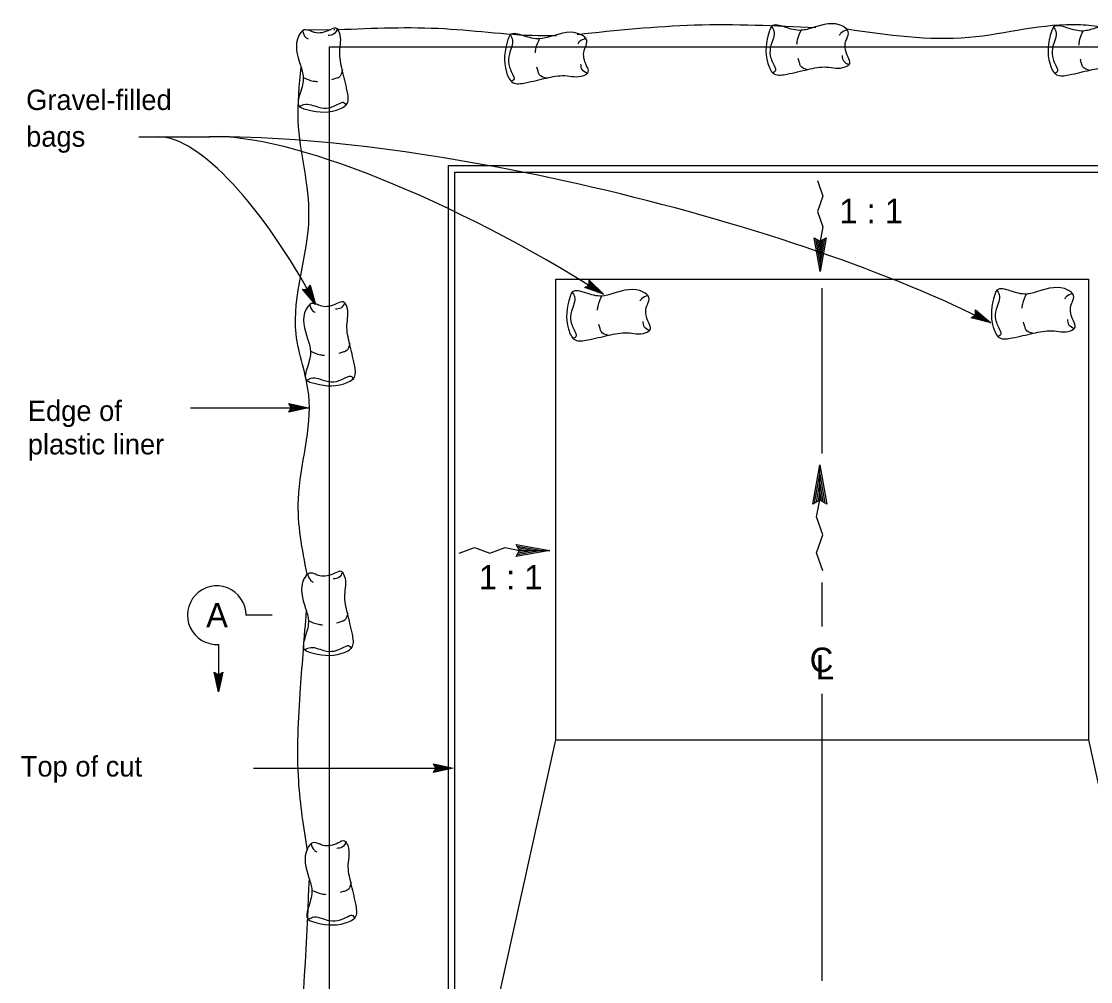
# Model space of a CAD drawing. Extents: x 6708826 to 6711089, y 1868571 to 1869537.
# Drawn here: x 6708829.8 to 6709144.3, y 1868819.1 to 1869101.6 of the extents above; entities that cross this region are included whole.
import ezdxf

# ---------------------------------------------------------------- set-up
doc = ezdxf.new("R2010")
doc.units = 0
for name, color, linetype in [('56 Stg 3 Anno', 7, 'Continuous'), ('57 Undefined', 7, 'Continuous'), ('60 Nongeo Data', 7, 'Continuous')]:
    doc.layers.add(name, color=color, linetype=linetype)

msp = doc.modelspace()

# ---------------------------------------------------------------- linework, layer by layer
at = {"layer": '56 Stg 3 Anno'}
for p, q in [((6708864.35, 1869067.62), (6708885.21, 1869067.62)), ((6709064.77, 1869028.01), (6709063.02, 1869037.91)), ((6709063.02, 1869037.91), (6709064.77, 1869036.89)), ((6709064.77, 1869030.38), (6709063.48, 1869037.64)), ((6709064.77, 1869032.73), (6709063.95, 1869037.36)), ((6709064.77, 1869035.13), (6709064.42, 1869037.09)), ((6709066.51, 1869037.91), (6709064.77, 1869028.01)), ((6709064.77, 1869036.89), (6709066.51, 1869037.91)), ((6709066.05, 1869037.64), (6709064.77, 1869030.38)), ((6709065.58, 1869037.36), (6709064.77, 1869032.73)), ((6709065.11, 1869037.09), (6709064.77, 1869035.13)), ((6708914, 1869022.68), (6708914.77, 1869023.97)), ((6708914.37, 1869023.26), (6708915.12, 1869020.62)), ((6708914.57, 1869023.63), (6708915.74, 1869019.46)), ((6708914.77, 1869023.97), (6708914.77, 1869023.97)), ((6708914.77, 1869023.97), (6708916.37, 1869018.29)), ((6708995.5, 1869023.3), (6708996.83, 1869023.97)), ((6709001.06, 1869021.32), (6708995.5, 1869023.3)), ((6708995.5, 1869023.3), (6708995.5, 1869023.3)), ((6708999.93, 1869022.03), (6708995.88, 1869023.47)), ((6708998.81, 1869022.73), (6708996.2, 1869023.66)), ((6708997.69, 1869023.44), (6708996.57, 1869023.84)), ((6708996.83, 1869023.97), (6708996.86, 1869025.47)), ((6708996.83, 1869024.29), (6708997.69, 1869023.44)), ((6708996.86, 1869025.47), (6708996.86, 1869025.47)), ((6708996.86, 1869025.47), (6709001.06, 1869021.32)), ((6708996.86, 1869025.07), (6708999.94, 1869022.03)), ((6708996.86, 1869024.66), (6708998.81, 1869022.73)), ((6708916.37, 1869018.29), (6708912.52, 1869022.75)), ((6708912.52, 1869022.75), (6708912.52, 1869022.75)), ((6708912.52, 1869022.75), (6708914, 1869022.68)), ((6708915.73, 1869019.46), (6708912.93, 1869022.72)), ((6708915.12, 1869020.62), (6708913.3, 1869022.73)), ((6708914.49, 1869021.79), (6708913.71, 1869022.69)), ((6708914.16, 1869022.96), (6708914.49, 1869021.79)), ((6709001.06, 1869021.32), (6709001.06, 1869021.32)), ((6709065.3, 1868974.39), (6709065.3, 1869023.08)), ((6708916.37, 1869018.29), (6708916.37, 1869018.29)), ((6709109.21, 1869014.39), (6709110.49, 1869015.17)), ((6709114.91, 1869012.86), (6709109.21, 1869014.39)), ((6709109.21, 1869014.39), (6709109.21, 1869014.39)), ((6709113.73, 1869013.47), (6709109.57, 1869014.59)), ((6709112.56, 1869014.09), (6709109.88, 1869014.81)), ((6709111.39, 1869014.7), (6709110.24, 1869015.01)), ((6709110.49, 1869015.17), (6709110.4, 1869016.66)), ((6709110.4, 1869016.66), (6709110.4, 1869016.66)), ((6709110.4, 1869016.66), (6709114.91, 1869012.86)), ((6709110.43, 1869016.26), (6709113.74, 1869013.47)), ((6709110.46, 1869015.48), (6709111.39, 1869014.7)), ((6709110.47, 1869015.85), (6709112.56, 1869014.09)), ((6709114.91, 1869012.86), (6709114.91, 1869012.86)), ((6708909.24, 1868987.85), (6708908.47, 1868989.14)), ((6708908.47, 1868989.14), (6708908.47, 1868989.14)), ((6708908.47, 1868989.14), (6708914.23, 1868987.85)), ((6708908.68, 1868988.8), (6708912.91, 1868987.85)), ((6708879.54, 1868987.85), (6708914.23, 1868987.85)), ((6708914.23, 1868987.85), (6708908.47, 1868986.58)), ((6708908.47, 1868986.58), (6708909.24, 1868987.85)), ((6708908.47, 1868986.58), (6708908.47, 1868986.58)), ((6708912.89, 1868987.85), (6708908.7, 1868986.92)), ((6708911.58, 1868987.85), (6708908.87, 1868987.25)), ((6708908.9, 1868988.45), (6708911.58, 1868987.85)), ((6708909.07, 1868988.12), (6708910.25, 1868987.86)), ((6708910.25, 1868987.86), (6708909.09, 1868987.6)), ((6708914.23, 1868987.85), (6708914.23, 1868987.85)), ((6709062.6, 1868959.55), (6709064.64, 1868971.09)), ((6709064.64, 1868971.09), (6709066.68, 1868959.55)), ((6709063.14, 1868959.86), (6709064.64, 1868968.33)), ((6709064.64, 1868968.33), (6709066.14, 1868959.86)), ((6709063.69, 1868960.18), (6709064.64, 1868965.59)), ((6709064.64, 1868965.59), (6709065.59, 1868960.18)), ((6709064.64, 1868960.73), (6709062.6, 1868959.55)), ((6709064.24, 1868960.5), (6709064.64, 1868962.78)), ((6709064.64, 1868962.78), (6709065.04, 1868960.5)), ((6709066.68, 1868959.55), (6709064.64, 1868960.73)), ((6708975.35, 1868947.67), (6708985.24, 1868945.92)), ((6708976.36, 1868945.92), (6708975.35, 1868947.67)), ((6708985.24, 1868945.92), (6708975.35, 1868944.18)), ((6708975.35, 1868944.18), (6708976.36, 1868945.92)), ((6708975.62, 1868947.21), (6708982.88, 1868945.92)), ((6708982.88, 1868945.92), (6708975.62, 1868944.64)), ((6708975.89, 1868946.74), (6708980.53, 1868945.92)), ((6708980.53, 1868945.92), (6708975.89, 1868945.11)), ((6708976.16, 1868946.27), (6708978.12, 1868945.92)), ((6708978.12, 1868945.92), (6708976.16, 1868945.58)), ((6709065.3, 1868923.55), (6709065.3, 1868936.5)), ((6708903.6, 1868926.88), (6708895.87, 1868926.88)), ((6708887.81, 1868918.26), (6708887.81, 1868904.33)), ((6708887.81, 1868904.33), (6708886.53, 1868910.09)), ((6708886.53, 1868910.09), (6708886.53, 1868910.09)), ((6708886.53, 1868910.09), (6708887.81, 1868909.32)), ((6708887.81, 1868909.32), (6708889.09, 1868910.09)), ((6708889.09, 1868910.09), (6708887.81, 1868904.33)), ((6708889.09, 1868910.09), (6708889.09, 1868910.09)), ((6708887.8, 1868905.66), (6708886.87, 1868909.86)), ((6708887.81, 1868906.98), (6708887.21, 1868909.69)), ((6708887.81, 1868908.31), (6708887.55, 1868909.47)), ((6708888.75, 1868909.88), (6708887.81, 1868905.65)), ((6708888.41, 1868909.66), (6708887.81, 1868906.98)), ((6708888.07, 1868909.49), (6708887.81, 1868908.31)), ((6708887.81, 1868904.33), (6708887.81, 1868904.33)), ((6709065.3, 1868819.27), (6709065.3, 1868903.71)), ((6708898.05, 1868881.86), (6708955.73, 1868881.86)), ((6708951.81, 1868881.86), (6708951.04, 1868883.15)), ((6708951.04, 1868883.15), (6708951.04, 1868883.15)), ((6708951.04, 1868883.15), (6708956.8, 1868881.86)), ((6708956.8, 1868881.86), (6708951.04, 1868880.58)), ((6708951.04, 1868880.58), (6708951.81, 1868881.86)), ((6708951.25, 1868882.81), (6708955.48, 1868881.86)), ((6708955.47, 1868881.86), (6708951.27, 1868880.93)), ((6708954.15, 1868881.86), (6708951.44, 1868881.26)), ((6708951.47, 1868882.46), (6708954.15, 1868881.86)), ((6708951.64, 1868882.13), (6708952.82, 1868881.86)), ((6708952.82, 1868881.86), (6708951.66, 1868881.61)), ((6708956.8, 1868881.86), (6708956.8, 1868881.86)), ((6708951.04, 1868880.59), (6708951.04, 1868880.59))]:
    msp.add_line(p, q, dxfattribs=at)
for points in [[(6709063.95, 1869054.7), (6709065.58, 1869050.17), (6709063.95, 1869045.64), (6709065.58, 1869041.11), (6709064.77, 1869036.89), (6709064.77, 1869028.01)], [(6709065.59, 1868939.96), (6709063.69, 1868945.24), (6709065.59, 1868950.53), (6709063.69, 1868955.81), (6709064.64, 1868960.73), (6709064.64, 1868971.09)], [(6708958.55, 1868945.11), (6708963.08, 1868946.74), (6708967.61, 1868945.11), (6708972.14, 1868946.74), (6708976.36, 1868945.92), (6708985.24, 1868945.92)]]:
    msp.add_lwpolyline(points, dxfattribs=at)
msp.add_arc((6708887.28, 1868926.87), 8.62, 0.1055, 273.4975, dxfattribs=at)
for centre, major_axis, ratio, start_param, end_param in [((6708899.83, 1868997.73), (33.1, -69.04), 0.3155, 1.718556, 2.986785), ((6708995.51, 1869014.62), (158.62, -38.37), 0.230593, 0.776019, 2.395591), ((6708971.44, 1869005.23), (98.85, -57.14), 0.254227, 1.415085, 2.758276)]:
    msp.add_ellipse(centre, major_axis=major_axis, ratio=ratio, start_param=start_param, end_param=end_param, dxfattribs=at)
at = {"layer": '60 Nongeo Data'}
for p, q in [((6708912.74, 1869099.06), (6708920.79, 1869099.13)), ((6708921.7, 1869099.13), (6708922, 1869099.14)), ((6708990.43, 1869097.55), (6708990.45, 1869097.56)), ((6708987.05, 1868890.2), (6709143.66, 1868890.2))]:
    msp.add_line(p, q, dxfattribs=at)
for points in [[(6708920.45, 1868713.46), (6708920.45, 1869094.08), (6709209.91, 1869094.08), (6709209.91, 1868713.46)], [(6708955.42, 1868754.11), (6708955.42, 1869059.11), (6709174.94, 1869059.11), (6709174.94, 1868765.65)], [(6708957.34, 1868756.03), (6708957.34, 1869057.19), (6709173.02, 1869057.19), (6709173.02, 1868756.03)], [(6708987.05, 1869025.72), (6709143.66, 1869025.72)], [(6708987.05, 1868890.2), (6708987.05, 1869025.72)], [(6709143.66, 1869025.72), (6709143.66, 1868890.2)], [(6708957.38, 1868756.31), (6708987.05, 1868890.2)], [(6709143.66, 1868890.2), (6709172.98, 1868757)]]:
    msp.add_lwpolyline(points, dxfattribs=at)
for points in [[(6708915.06, 1869098.66), (6708913.02, 1869099.03), (6708911.43, 1869097.37), (6708911.88, 1869088.69), (6708912.71, 1869085.14), (6708911.81, 1869080.39), (6708911.65, 1869076.46), (6708912.94, 1869075.86), (6708922.55, 1869075.48), (6708925.65, 1869077.44), (6708925.65, 1869081.07), (6708924.21, 1869087.26), (6708923.46, 1869092.69), (6708923.38, 1869098.2), (6708922.32, 1869099.56), (6708920.51, 1869099.03), (6708916.04, 1869098.28), (6708914.83, 1869098.73)], [(6708912.49, 1869098.81), (6708913.47, 1869096.84), (6708914.15, 1869096.39)], [(6708922.85, 1869099.41), (6708921.64, 1869097.75), (6708920.05, 1869097.37)], [(6708922.89, 1869099.14), (6708954.23, 1869099.42), (6708983.7, 1869097.39), (6708987.22, 1869097.43)], [(6708995.72, 1869093.94), (6708996.11, 1869095.98), (6708994.47, 1869097.58), (6708985.78, 1869097.2), (6708982.23, 1869096.4), (6708977.48, 1869097.34), (6708973.55, 1869097.52), (6708972.94, 1869096.24), (6708972.48, 1869086.64), (6708974.42, 1869083.52), (6708978.05, 1869083.49), (6708984.25, 1869084.88), (6708989.69, 1869085.59), (6708995.2, 1869085.62), (6708996.57, 1869086.67), (6708996.06, 1869088.49), (6708995.34, 1869092.96), (6708995.8, 1869094.17)], [(6708993.28, 1869097.73), (6709027.81, 1869100.5), (6709063.48, 1869099.77)], [(6709072.63, 1869096.47), (6709073.03, 1869098.51), (6709071.38, 1869100.11), (6709062.69, 1869099.73), (6709059.14, 1869098.92), (6709054.39, 1869099.87), (6709050.47, 1869100.05), (6709049.85, 1869098.77), (6709049.4, 1869089.16), (6709051.34, 1869086.05), (6709054.96, 1869086.02), (6709061.16, 1869087.41), (6709066.6, 1869088.12), (6709072.11, 1869088.15), (6709073.48, 1869089.2), (6709072.97, 1869091.02), (6709072.25, 1869095.49), (6709072.71, 1869096.7)], [(6709050.47, 1869100.13), (6709051.13, 1869098.76), (6709050.27, 1869094.45), (6709050.09, 1869091.43), (6709051.43, 1869088.09), (6709051.65, 1869087.18), (6709050.66, 1869086.35)], [(6709059.14, 1869099), (6709057.98, 1869095.98), (6709057.82, 1869094.77)], [(6709072.81, 1869099.04), (6709070.84, 1869098.07), (6709070.38, 1869097.4)], [(6709072.66, 1869099.34), (6709108.46, 1869096.89), (6709141.34, 1869100.6), (6709147.79, 1869099.97)], [(6709155.6, 1869096.27), (6709155.99, 1869098.31), (6709154.34, 1869099.91), (6709145.66, 1869099.53), (6709142.1, 1869098.72), (6709137.35, 1869099.67), (6709133.43, 1869099.85), (6709132.81, 1869098.57), (6709132.36, 1869088.97), (6709134.3, 1869085.85), (6709137.92, 1869085.82), (6709144.13, 1869087.21), (6709149.57, 1869087.92), (6709155.08, 1869087.95), (6709156.45, 1869089), (6709155.93, 1869090.82), (6709155.21, 1869095.29), (6709155.68, 1869096.5)], [(6709133.43, 1869099.93), (6709134.1, 1869098.56), (6709133.23, 1869094.26), (6709133.06, 1869091.23), (6709134.39, 1869087.89), (6709134.61, 1869086.98), (6709133.62, 1869086.16)], [(6709142.1, 1869098.8), (6709140.95, 1869095.78), (6709140.79, 1869094.57)], [(6708973.55, 1869097.6), (6708974.22, 1869096.23), (6708973.36, 1869091.93), (6708973.18, 1869088.9), (6708974.51, 1869085.56), (6708974.73, 1869084.65), (6708973.75, 1869083.83)], [(6708982.23, 1869096.47), (6708981.07, 1869093.45), (6708980.91, 1869092.25)], [(6708995.89, 1869096.51), (6708993.92, 1869095.55), (6708993.46, 1869094.87)], [(6709061.24, 1869087.33), (6709058.98, 1869088.48), (6709058.69, 1869089.39), (6709058.32, 1869090.61)], [(6709073.33, 1869088.67), (6709071.68, 1869089.89), (6709071.31, 1869091.49)], [(6709144.2, 1869087.13), (6709141.94, 1869088.28), (6709141.65, 1869089.19), (6709141.28, 1869090.41)], [(6708913.83, 1868938.92), (6708911.3, 1868960.97), (6708914.33, 1868991.7), (6708910.64, 1869009.6), (6708914.41, 1869044.07), (6708911.27, 1869072.32), (6708912.14, 1869088.07)], [(6708924.29, 1869087.33), (6708923.15, 1869085.07), (6708922.25, 1869084.76), (6708921.03, 1869084.39)], [(6708984.32, 1869084.8), (6708982.07, 1869085.96), (6708981.77, 1869086.87), (6708981.4, 1869088.08)], [(6708996.41, 1869086.14), (6708994.76, 1869087.37), (6708994.4, 1869088.96)], [(6708912.64, 1869085.14), (6708915.66, 1869084.01), (6708916.87, 1869083.86)], [(6708911.58, 1869076.46), (6708912.94, 1869077.14), (6708917.25, 1869076.31), (6708920.28, 1869076.16), (6708923.61, 1869077.52), (6708924.51, 1869077.74), (6708925.35, 1869076.76)], [(6709013.99, 1869018.29), (6709014.39, 1869020.33), (6709012.74, 1869021.94), (6709004.05, 1869021.55), (6709000.5, 1869020.75), (6708995.75, 1869021.69), (6708991.82, 1869021.87), (6708991.21, 1869020.59), (6708990.76, 1869010.99), (6708992.69, 1869007.87), (6708996.32, 1869007.84), (6709002.52, 1869009.23), (6709007.96, 1869009.94), (6709013.47, 1869009.98), (6709014.84, 1869011.02), (6709014.33, 1869012.84), (6709013.61, 1869017.31), (6709014.07, 1869018.52)], [(6709138.9, 1869018.88), (6709139.3, 1869020.92), (6709137.65, 1869022.52), (6709128.96, 1869022.14), (6709125.41, 1869021.33), (6709120.66, 1869022.28), (6709116.73, 1869022.46), (6709116.12, 1869021.18), (6709115.67, 1869011.58), (6709117.6, 1869008.46), (6709121.23, 1869008.43), (6709127.43, 1869009.82), (6709132.87, 1869010.53), (6709138.38, 1869010.56), (6709139.75, 1869011.61), (6709139.24, 1869013.43), (6709138.52, 1869017.9), (6709138.98, 1869019.11)], [(6708991.82, 1869021.95), (6708992.49, 1869020.58), (6708991.63, 1869016.28), (6708991.45, 1869013.25), (6708992.79, 1869009.91), (6708993.01, 1869009), (6708992.02, 1869008.18)], [(6709000.5, 1869020.82), (6708999.34, 1869017.81), (6708999.18, 1869016.6)], [(6709014.16, 1869020.86), (6709012.19, 1869019.9), (6709011.74, 1869019.22)], [(6709116.73, 1869022.54), (6709117.4, 1869021.17), (6709116.54, 1869016.87), (6709116.36, 1869013.84), (6709117.7, 1869010.5), (6709117.91, 1869009.59), (6709116.93, 1869008.77)], [(6709125.41, 1869021.41), (6709124.25, 1869018.39), (6709124.09, 1869017.18)], [(6709139.07, 1869021.45), (6709137.1, 1869020.48), (6709136.64, 1869019.81)], [(6708917.18, 1869018.14), (6708915.14, 1869018.52), (6708913.55, 1869016.85), (6708914.01, 1869008.17), (6708914.84, 1869004.62), (6708913.93, 1868999.87), (6708913.78, 1868995.94), (6708915.06, 1868995.34), (6708924.67, 1868994.96), (6708927.77, 1868996.92), (6708927.77, 1869000.55), (6708926.34, 1869006.74), (6708925.58, 1869012.17), (6708925.5, 1869017.69), (6708924.45, 1869019.04), (6708922.63, 1869018.52), (6708918.17, 1869017.76), (6708916.96, 1869018.21)], [(6708914.61, 1869018.29), (6708915.59, 1869016.33), (6708916.27, 1869015.87)], [(6708924.98, 1869018.89), (6708923.76, 1869017.23), (6708922.18, 1869016.85)], [(6709139.6, 1869011.08), (6709137.94, 1869012.31), (6709137.58, 1869013.9)], [(6709002.6, 1869009.15), (6709000.34, 1869010.31), (6709000.04, 1869011.22), (6708999.68, 1869012.43)], [(6709014.69, 1869010.5), (6709013.04, 1869011.72), (6709012.67, 1869013.31)], [(6709127.5, 1869009.74), (6709125.25, 1869010.89), (6709124.95, 1869011.8), (6709124.59, 1869013.02)], [(6708914.76, 1869004.62), (6708917.79, 1869003.49), (6708919, 1869003.34)], [(6708926.41, 1869006.81), (6708925.28, 1869004.55), (6708924.37, 1869004.25), (6708923.16, 1869003.87)], [(6708913.7, 1868995.94), (6708915.06, 1868996.62), (6708919.38, 1868995.79), (6708922.4, 1868995.64), (6708925.73, 1868997), (6708926.64, 1868997.22), (6708927.47, 1868996.24)], [(6708916.58, 1868938.83), (6708914.53, 1868939.21), (6708912.94, 1868937.55), (6708913.4, 1868928.87), (6708914.23, 1868925.32), (6708913.32, 1868920.56), (6708913.17, 1868916.63), (6708914.46, 1868916.03), (6708924.07, 1868915.65), (6708927.17, 1868917.62), (6708927.17, 1868921.24), (6708925.73, 1868927.43), (6708924.97, 1868932.87), (6708924.9, 1868938.38), (6708923.84, 1868939.74), (6708922.02, 1868939.21), (6708917.56, 1868938.45), (6708916.35, 1868938.91)], [(6708914, 1868938.98), (6708914.99, 1868937.02), (6708915.67, 1868936.57)], [(6708924.37, 1868939.59), (6708923.16, 1868937.92), (6708921.57, 1868937.55)], [(6708913.99, 1868857.66), (6708911.38, 1868877.95), (6708911.94, 1868905.46), (6708913.68, 1868928.11)], [(6708925.81, 1868927.51), (6708924.67, 1868925.24), (6708923.76, 1868924.94), (6708922.55, 1868924.56)], [(6708914.16, 1868925.32), (6708917.18, 1868924.18), (6708918.39, 1868924.03)], [(6708913.1, 1868916.63), (6708914.46, 1868917.31), (6708918.77, 1868916.48), (6708921.8, 1868916.33), (6708925.12, 1868917.69), (6708926.03, 1868917.92), (6708926.86, 1868916.94)], [(6708917.59, 1868859.52), (6708915.55, 1868859.9), (6708913.96, 1868858.24), (6708914.41, 1868849.56), (6708915.24, 1868846.01), (6708914.34, 1868841.25), (6708914.18, 1868837.33), (6708915.47, 1868836.72), (6708925.08, 1868836.34), (6708928.18, 1868838.31), (6708928.18, 1868841.93), (6708926.74, 1868848.12), (6708925.98, 1868853.56), (6708925.91, 1868859.07), (6708924.85, 1868860.43), (6708923.03, 1868859.9), (6708918.57, 1868859.15), (6708917.36, 1868859.6)], [(6708915.02, 1868859.67), (6708916, 1868857.71), (6708916.68, 1868857.26)], [(6708925.38, 1868860.28), (6708924.17, 1868858.62), (6708922.58, 1868858.24)], [(6708911.04, 1868785.99), (6708914.48, 1868847.99), (6708914.52, 1868848.93)], [(6708926.82, 1868848.2), (6708925.68, 1868845.93), (6708924.77, 1868845.63), (6708923.56, 1868845.25)], [(6708915.17, 1868846.01), (6708918.19, 1868844.88), (6708919.4, 1868844.73)], [(6708914.11, 1868837.33), (6708915.47, 1868838.01), (6708919.78, 1868837.18), (6708922.81, 1868837.02), (6708926.14, 1868838.38), (6708927.04, 1868838.61), (6708927.88, 1868837.63)]]:
    msp.add_spline(points, degree=3, dxfattribs=at)

# ---------------------------------------------------------------- texts
at = {"layer": '57 Undefined'}
for s, height, p in [('Gravel-filled', 6, (6708831.22, 1869075.48)), ('bags', 6, (6708831.22, 1869064.68)), ('1 : 1', 7.2, (6709070.4, 1869042.19)), ('Edge of', 6, (6708831.71, 1868984)), ('plastic liner', 6, (6708831.71, 1868974.16)), ('1 : 1', 7.2, (6708964.36, 1868934.43)), ('A', 7.21, (6708884.15, 1868923.27)), ('C', 7.2, (6709061.67, 1868910.14)), ('L', 7.2, (6709063.47, 1868907.95)), ('Top of cut', 6, (6708829.64, 1868879.4))]:
    msp.add_text(s, height=height, dxfattribs=at).set_placement(p)

doc.saveas('drawing.dxf')
